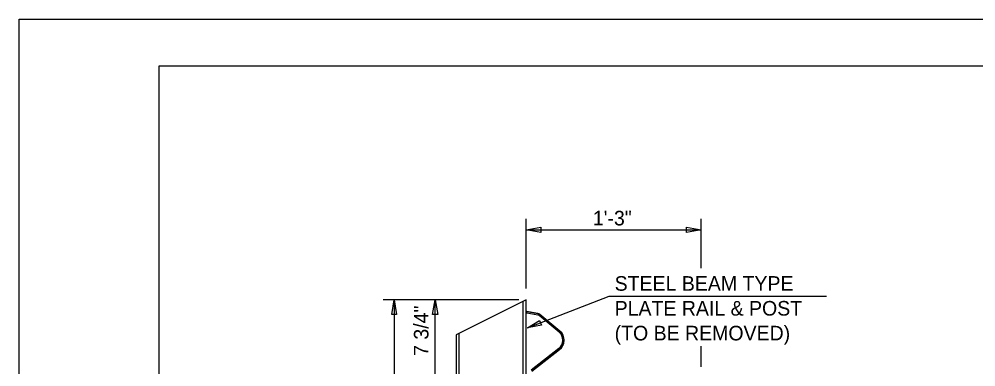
# Model space of a CAD drawing. Extents: x 0 to 22.7, y 0 to 15.7.
# Drawn here: x 0 to 6.83, y 12.19 to 14.67 of the extents above; entities that cross this region are included whole.
import ezdxf

# ---------------------------------------------------------------- set-up
doc = ezdxf.new("R2010")
doc.units = 0
for name, color, linetype in [('BORDER_ANNO_Cutsheet', 7, 'Continuous'), ('BRDG_ANNO_Anno-Sheet', 7, 'Continuous'), ('BRDG_ANNO_General-Notes', 7, 'Continuous'), ('BRDG_BASE_Obj-Line', 7, 'Continuous'), ('BRDG_BASE_Pattern', 7, 'Continuous'), ('Default', 7, 'Continuous')]:
    doc.layers.add(name, color=color, linetype=linetype)

# ---------------------------------------------------------------- blocks, each defined once
blk = doc.blocks.new('TERM')
at = {"layer": 'Default'}
for p, q in [((-1.6, -0.267), (-1.6, 0.267)), ((-1.6, 0.267), (0, 0)), ((0, 0), (-1.6, -0.267))]:
    blk.add_line(p, q, dxfattribs=at)

msp = doc.modelspace()

# ---------------------------------------------------------------- linework, layer by layer
at = {"layer": 'BORDER_ANNO_Cutsheet'}
msp.add_lwpolyline([(0, 14.6667), (22.6667, 14.6667), (22.6667, 0), (0, 0)], close=True, dxfattribs=at)
at = {"layer": 'BRDG_ANNO_Anno-Sheet'}
msp.add_lwpolyline([(1, 14.3333), (22.3333, 14.3333), (22.3333, 0.3333), (1, 0.3333)], close=True, dxfattribs=at)
at = {"layer": 'BRDG_ANNO_General-Notes'}
for p, q in [((3.6217, 12.7445), (3.6217, 13.2413)), ((4.8717, 12.8907), (4.8717, 13.2413)), ((3.6217, 13.1632), (4.8717, 13.1632)), ((2.9093, 12.6642), (2.6009, 12.6642)), ((2.6791, 12.6642), (2.6791, 9.5809)), ((3.5696, 12.6642), (2.8938, 12.6642)), ((2.9719, 12.0392), (2.9719, 12.6642)), ((3.6308, 12.464), (3.7173, 12.5174)), ((3.7173, 12.5174), (3.7308, 12.4824)), ((3.7308, 12.4824), (3.6308, 12.464)), ((2.9719, 10.7059), (2.9719, 12.3309)), ((4.8717, 12.1866), (4.8717, 12.3326))]:
    msp.add_line(p, q, dxfattribs=at)
msp.add_lwpolyline([(3.6308, 12.464), (4.2154, 12.6896), (5.7664, 12.6896)], dxfattribs=at)
at = {"layer": 'BRDG_BASE_Obj-Line'}
for p, q in [((3.6217, 12.6642), (3.1217, 12.4142)), ((3.6008, 9.5913), (3.6008, 12.6538)), ((3.6217, 9.5809), (3.6217, 12.6642)), ((3.6253, 12.5714), (3.6269, 12.5809)), ((3.6269, 12.5809), (3.7057, 12.5661)), ((3.6253, 12.5714), (3.7039, 12.5567)), ((3.8567, 12.4341), (3.7137, 12.5521)), ((3.8623, 12.4418), (3.7194, 12.5597)), ((3.1217, 12.4142), (3.1217, 9.8309)), ((3.1425, 9.8205), (3.1425, 12.4246)), ((3.8551, 12.3173), (3.6573, 12.1636)), ((3.8605, 12.3095), (3.6628, 12.1558))]:
    msp.add_line(p, q, dxfattribs=at)
for centre, major_axis, start_param, end_param in [((3.7001, 12.5335), (0, 0.0235), 5.622127, 6.109725), ((3.7002, 12.5335), (0, 0.0332), 5.623441, 6.108747), ((3.8144, 12.3764), (0, 0.0829), 3.773625, 5.62261), ((3.8144, 12.3764), (0, 0.0732), 3.773625, 5.62261)]:
    msp.add_ellipse(centre, major_axis=major_axis, ratio=0.942308, start_param=start_param, end_param=end_param, dxfattribs=at)
at = {"layer": 'BRDG_BASE_Pattern'}
msp.add_lwpolyline([(3.6628, 12.1558), (3.8605, 12.3095), (3.8857, 12.342), (3.8922, 12.3793), (3.8857, 12.4119), (3.8623, 12.4418), (3.7194, 12.5597), (3.7057, 12.5661), (3.6269, 12.5809), (3.6217, 12.5809), (3.6217, 12.6642), (3.1217, 12.4142), (3.1217, 9.8309)], dxfattribs=at)

# ---------------------------------------------------------------- block references
at = {"layer": 'BRDG_ANNO_General-Notes', "xscale": 0.06510416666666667}
for p, yscale, rotation in [((3.6217, 13.1632), 0.0732421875, 180), ((2.6791, 12.6642), 0.06510416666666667, 90), ((2.9719, 12.6642), 0.0732421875, 90)]:
    msp.add_blockref('TERM', p, dxfattribs=dict(at, yscale=yscale, rotation=rotation))
at = {"layer": 'BRDG_ANNO_General-Notes', "xscale": 0.06510416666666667, "yscale": 0.0732421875}
msp.add_blockref('TERM', (4.8717, 13.1632), dxfattribs=at)

# ---------------------------------------------------------------- texts
at = {"layer": 'BRDG_ANNO_General-Notes'}
for s, height, p in [('1\'-3"', 0.10417, (4.0983, 13.1952)), ('STEEL BEAM TYPE', 0.104167, (4.2536, 12.729)), ('PLATE RAIL & POST', 0.104167, (4.2536, 12.5519)), ('(TO BE REMOVED)', 0.104167, (4.2536, 12.3748))]:
    msp.add_text(s, height=height, dxfattribs=at).set_placement(p)
msp.add_text('7 3/4"', height=0.10417, rotation=90, dxfattribs=at).set_placement((2.9239, 12.2642))

doc.saveas('drawing.dxf')
